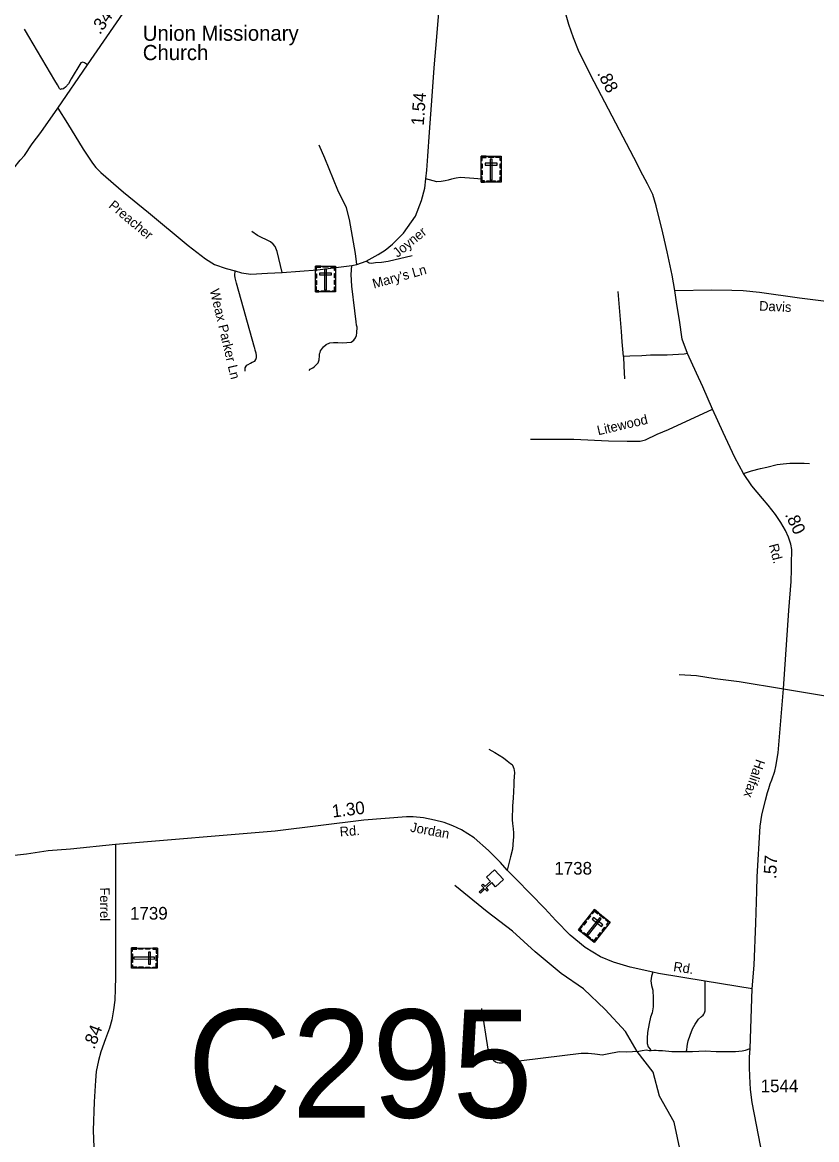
# Model space of a CAD drawing. Extents: x 2220236 to 2384410, y 720751 to 894131.
# Drawn here: x 2332948 to 2340787, y 767564 to 778583 of the extents above; entities that cross this region are included whole.
import ezdxf

# ---------------------------------------------------------------- set-up
doc = ezdxf.new("R2010")
doc.units = 0
doc.layers.add('Default', color=7, linetype='Continuous')

msp = doc.modelspace()

# ---------------------------------------------------------------- linework, layer by layer
at = {"layer": 'Default'}
for points in [[(2333299, 777738), (2333591, 778165), (2333943, 778675), (2334238, 779104), (2334327, 779223)], [(2333299, 777738), (2333395, 777586), (2333549, 777333), (2333641, 777194), (2333675, 777150), (2333722, 777102), (2333946, 776908), (2334192, 776707), (2334584, 776381), (2334757, 776249), (2334846, 776196), (2334961, 776155), (2335050, 776131), (2335111, 776112), (2335204, 776101), (2335367, 776108), (2335511, 776117), (2335861, 776142), (2336199, 776186), (2336248, 776194), (2336342, 776229), (2336459, 776293), (2336528, 776336), (2336600, 776395), (2336710, 776503), (2336827, 776670), (2336886, 776825), (2336919, 776948), (2336931, 777039), (2336941, 777124), (2336950, 777262), (2336967, 777500), (2336994, 777854), (2337013, 778133), (2337040, 778439), (2337070, 778840)], [(2339388, 775939), (2339362, 776088), (2339312, 776320), (2339270, 776507), (2339202, 776774), (2339169, 776885), (2339116, 776991), (2339072, 777077), (2338984, 777249), (2338590, 777996), (2338515, 778143), (2338438, 778306), (2338387, 778429), (2338341, 778560), (2338291, 778736)], [(2333591, 778165), (2333561, 778183), (2333544, 778189), (2333537, 778188), (2333527, 778182), (2333431, 778025), (2333404, 777978), (2333374, 777943), (2333357, 777931), (2333349, 777925), (2333339, 777926), (2333326, 777921), (2333315, 777931), (2333294, 777966), (2333270, 778009), (2332969, 778514)], [(2331904, 776214), (2331951, 776264), (2332056, 776374), (2332110, 776417), (2332152, 776461), (2332191, 776495), (2332228, 776529), (2332263, 776561), (2332325, 776621), (2332388, 776676), (2332460, 776743), (2332592, 776865), (2332660, 776932), (2332690, 776962), (2332713, 776987), (2332745, 777021), (2332811, 777088), (2332864, 777146), (2332928, 777223), (2332971, 777271), (2333046, 777384), (2333130, 777498), (2333299, 777738)], [(2336248, 776194), (2336235, 776302), (2336177, 776639), (2336146, 776752), (2336063, 776929), (2335934, 777244), (2335878, 777373)], [(2337482, 777037), (2337405, 777044), (2337273, 777052), (2337230, 777046), (2337182, 777035), (2337152, 777025), (2337120, 777020), (2337080, 777012), (2337040, 777011), (2336931, 777039)], [(2335511, 776117), (2335464, 776323), (2335442, 776371), (2335425, 776395), (2335397, 776417), (2335269, 776481), (2335213, 776519)], [(2336795, 776280), (2336560, 776224), (2336491, 776215), (2336432, 776210), (2336395, 776203), (2336370, 776207), (2336342, 776229)], [(2335778, 775151), (2335790, 775161), (2335814, 775175), (2335833, 775189), (2335867, 775226), (2335879, 775256), (2335882, 775294), (2335882, 775314), (2335886, 775328), (2335892, 775344), (2335902, 775357), (2335920, 775382), (2335921, 775382), (2335948, 775407), (2335983, 775421), (2336019, 775426), (2336061, 775426), (2336108, 775423), (2336192, 775430), (2336221, 775450), (2336237, 775470), (2336245, 775494), (2336248, 775520), (2336252, 775578), (2336245, 775598), (2336242, 775629), (2336231, 775737), (2336199, 775981), (2336192, 776095), (2336199, 776186)], [(2335146, 775143), (2335148, 775175), (2335156, 775193), (2335164, 775201), (2335178, 775209), (2335199, 775222), (2335215, 775230), (2335242, 775242), (2335253, 775259), (2335258, 775278), (2335258, 775297), (2335255, 775320), (2335246, 775351), (2335242, 775370), (2335241, 775377), (2335061, 776010), (2335048, 776063), (2335046, 776086), (2335050, 776131)], [(2339388, 775939), (2339752, 775944), (2339950, 775943), (2340062, 775938), (2340222, 775922), (2340619, 775867), (2341406, 775766)], [(2340458, 772010), (2340511, 772783), (2340534, 773068), (2340540, 773186), (2340540, 773240), (2340543, 773385), (2340533, 773437), (2340508, 773506), (2340478, 773570), (2340434, 773649), (2340380, 773728), (2340307, 773821), (2340251, 773887), (2340148, 774013), (2340066, 774135), (2339978, 774291), (2339864, 774538), (2339759, 774769), (2339664, 774987), (2339601, 775123), (2339511, 775317), (2339460, 775458), (2339432, 775647), (2339408, 775799), (2339388, 775939)], [(2338882, 775287), (2338866, 775433), (2338861, 775533), (2338827, 775929)], [(2339511, 775317), (2339479, 775311), (2339425, 775306), (2339310, 775301), (2339146, 775299), (2339060, 775295), (2338944, 775291), (2338882, 775287)], [(2338882, 775287), (2338883, 775193), (2338891, 775066)], [(2337963, 774472), (2338392, 774471), (2338732, 774455), (2338917, 774451), (2338998, 774453), (2339046, 774453), (2339099, 774467), (2339214, 774523), (2339324, 774568), (2339759, 774769)], [(2340066, 774135), (2340145, 774161), (2340232, 774182), (2340294, 774195), (2340397, 774221), (2340457, 774229), (2340523, 774234), (2340589, 774237), (2340663, 774236), (2340717, 774232)], [(2339431, 772150), (2339602, 772142), (2339785, 772113), (2340023, 772081), (2340458, 772010)], [(2340150, 769052), (2340171, 769284), (2340187, 769700), (2340196, 770016), (2340200, 770157), (2340228, 770655), (2340245, 770764), (2340281, 770911), (2340302, 770988), (2340315, 771026), (2340328, 771072), (2340343, 771114), (2340373, 771199), (2340383, 771244), (2340407, 771378), (2340415, 771459), (2340458, 772010)], [(2340458, 772010), (2343353, 771527), (2343573, 771495), (2343812, 771451)], [(2337551, 771416), (2337612, 771382), (2337697, 771328), (2337733, 771300), (2337767, 771275), (2337781, 771263), (2337792, 771242), (2337800, 771224), (2337805, 771184), (2337800, 771100), (2337799, 771062), (2337794, 770996), (2337791, 770931), (2337786, 770855), (2337781, 770718), (2337784, 770681), (2337787, 770656), (2337791, 770631), (2337794, 770589), (2337795, 770547), (2337791, 770519), (2337784, 770429), (2337765, 770352), (2337734, 770222)], [(2333869, 770476), (2333425, 770429), (2333204, 770411), (2332990, 770380), (2332365, 770309), (2332145, 770287), (2332083, 770284), (2331985, 770285), (2331867, 770304), (2331759, 770325), (2331647, 770356), (2331534, 770399), (2331422, 770447), (2331331, 770496), (2331223, 770569), (2331114, 770648), (2331027, 770713), (2330897, 770816)], [(2340150, 769052), (2339688, 769128), (2339226, 769204), (2339169, 769217), (2338946, 769265), (2338782, 769316), (2338654, 769368), (2338504, 769459), (2338356, 769580), (2338214, 769724), (2338103, 769845), (2337821, 770134), (2337734, 770222), (2337667, 770296), (2337550, 770415), (2337407, 770541), (2337281, 770619), (2337195, 770658), (2337111, 770692), (2337016, 770716), (2336907, 770737), (2336804, 770748), (2336740, 770748), (2336319, 770715), (2335443, 770608), (2333869, 770476)], [(2333869, 770476), (2333869, 769168), (2333866, 769052), (2333861, 768940), (2333848, 768844), (2333830, 768746), (2333807, 768664), (2333768, 768560), (2333724, 768430), (2333700, 768346), (2333676, 768235), (2333669, 768146), (2333656, 767936), (2333647, 767656), (2333688, 766661), (2333684, 766078)], [(2339448, 767426), (2339379, 767737), (2339237, 767994), (2339172, 768229), (2339014, 768435), (2338900, 768631), (2338699, 768848), (2338485, 769051), (2338266, 769204), (2338009, 769418), (2337784, 769621), (2337536, 769810), (2337217, 770071)], [(2339169, 769217), (2339157, 769175), (2339152, 769129), (2339157, 769084), (2339170, 769037), (2339173, 768961), (2339175, 768874), (2339164, 768816), (2339147, 768771), (2339135, 768710), (2339119, 768621), (2339114, 768565), (2339114, 768514), (2339124, 768481), (2339140, 768460), (2339151, 768445)], [(2339498, 768433), (2339505, 768451), (2339510, 768484), (2339512, 768507), (2339519, 768538), (2339538, 768594), (2339563, 768657), (2339587, 768704), (2339622, 768753), (2339650, 768778), (2339667, 768792), (2339674, 768801), (2339681, 768815), (2339687, 768834), (2339687, 768869), (2339687, 769028), (2339688, 769128)], [(2340254, 767387), (2340151, 767932), (2340134, 768060), (2340129, 768125), (2340126, 768191), (2340124, 768275), (2340124, 768376), (2340130, 768462), (2340150, 769052)], [(2337479, 768856), (2337542, 768457), (2337554, 768421), (2337570, 768393), (2337597, 768349), (2337617, 768331), (2337635, 768324), (2337654, 768322), (2337685, 768321), (2338462, 768416), (2338533, 768417), (2338599, 768411), (2338623, 768406), (2338647, 768404), (2338670, 768401), (2338721, 768409), (2338837, 768432), (2338908, 768430), (2339031, 768437), (2339065, 768444), (2339108, 768449), (2339134, 768445), (2339151, 768445)], [(2339151, 768445), (2339155, 768445), (2339179, 768446), (2339202, 768447), (2339227, 768445), (2339265, 768445), (2339356, 768435), (2339423, 768433), (2339498, 768433)], [(2339498, 768433), (2339563, 768433), (2339685, 768441), (2339796, 768433), (2339901, 768433), (2339986, 768435), (2340053, 768440), (2340085, 768448), (2340130, 768462)]]:
    msp.add_lwpolyline(points, dxfattribs=at)
for points in [[(2337475, 777262), (2337674, 777262), (2337674, 777008), (2337475, 777008)], [(2337475, 777219), (2337486, 777219), (2337486, 777251), (2337527, 777251), (2337527, 777262), (2337475, 777262)], [(2337549, 777262), (2337601, 777262), (2337601, 777251), (2337549, 777251)], [(2337674, 777219), (2337663, 777219), (2337663, 777251), (2337622, 777251), (2337622, 777262), (2337674, 777262)], [(2337475, 777145), (2337475, 777188), (2337486, 777188), (2337486, 777145)], [(2337516, 777194), (2337516, 777176), (2337634, 777176), (2337634, 777194)], [(2337584, 777233), (2337565, 777233), (2337565, 777030), (2337584, 777030)], [(2337663, 777146), (2337663, 777189), (2337674, 777189), (2337674, 777146)], [(2337475, 777078), (2337475, 777121), (2337486, 777121), (2337486, 777078)], [(2337508, 777008), (2337508, 777019), (2337486, 777019), (2337486, 777060), (2337475, 777060), (2337475, 777008)], [(2337641, 777008), (2337641, 777019), (2337663, 777019), (2337663, 777060), (2337674, 777060), (2337674, 777008)], [(2337663, 777080), (2337663, 777123), (2337674, 777123), (2337674, 777080)], [(2337532, 777019), (2337617, 777019), (2337617, 777008), (2337532, 777008)], [(2335841, 776179), (2336040, 776179), (2336040, 775924), (2335841, 775924)], [(2335841, 776135), (2335852, 776135), (2335852, 776167), (2335893, 776167), (2335893, 776179), (2335841, 776179)], [(2335915, 776178), (2335967, 776178), (2335967, 776167), (2335915, 776167)], [(2336040, 776135), (2336028, 776135), (2336028, 776167), (2335988, 776167), (2335988, 776178), (2336040, 776178)], [(2335841, 776061), (2335841, 776104), (2335852, 776104), (2335852, 776061)], [(2335881, 776110), (2335881, 776092), (2335999, 776092), (2335999, 776110)], [(2335950, 776149), (2335931, 776149), (2335931, 775946), (2335950, 775946)], [(2336028, 776062), (2336028, 776105), (2336040, 776105), (2336040, 776062)], [(2335841, 775994), (2335841, 776037), (2335852, 776037), (2335852, 775994)], [(2335874, 775924), (2335874, 775935), (2335852, 775935), (2335852, 775976), (2335841, 775976), (2335841, 775924)], [(2336007, 775924), (2336007, 775935), (2336029, 775935), (2336029, 775976), (2336040, 775976), (2336040, 775924)], [(2336028, 775996), (2336028, 776039), (2336040, 776039), (2336040, 775996)], [(2335898, 775935), (2335983, 775935), (2335983, 775924), (2335898, 775924)], [(2337619, 770058), (2337580, 770100), (2337524, 770048), (2337546, 770024), (2337534, 770014), (2337512, 770037), (2337468, 769996), (2337457, 770008), (2337501, 770049), (2337480, 770072), (2337491, 770083), (2337513, 770060), (2337569, 770111), (2337530, 770154), (2337608, 770226), (2337697, 770130)], [(2338594, 769833), (2338750, 769710), (2338592, 769510), (2338436, 769634)], [(2338521, 769741), (2338548, 769775), (2338557, 769768), (2338530, 769734)], [(2338567, 769799), (2338576, 769792), (2338596, 769818), (2338627, 769792), (2338634, 769801), (2338594, 769833)], [(2338652, 769787), (2338692, 769755), (2338685, 769746), (2338645, 769778)], [(2338462, 769613), (2338469, 769622), (2338451, 769636), (2338477, 769668), (2338468, 769674), (2338436, 769634)], [(2338479, 769689), (2338506, 769723), (2338515, 769715), (2338488, 769681)], [(2338661, 769743), (2338646, 769754), (2338520, 769595), (2338535, 769584)], [(2338583, 769755), (2338572, 769740), (2338664, 769667), (2338676, 769682)], [(2338669, 769626), (2338695, 769660), (2338704, 769652), (2338678, 769618)], [(2338723, 769676), (2338714, 769683), (2338734, 769708), (2338702, 769733), (2338709, 769742), (2338750, 769710)], [(2338488, 769607), (2338554, 769554), (2338547, 769545), (2338481, 769598)], [(2338566, 769531), (2338573, 769540), (2338590, 769526), (2338615, 769558), (2338624, 769551), (2338592, 769510)], [(2338628, 769574), (2338655, 769608), (2338663, 769601), (2338637, 769567)], [(2334281, 769454), (2334280, 769255), (2334025, 769256), (2334026, 769455)], [(2334026, 769422), (2334037, 769422), (2334037, 769444), (2334078, 769443), (2334078, 769455), (2334026, 769455)], [(2334096, 769454), (2334139, 769454), (2334139, 769443), (2334096, 769443)], [(2334163, 769454), (2334206, 769454), (2334206, 769443), (2334163, 769443)], [(2334237, 769454), (2334237, 769442), (2334269, 769442), (2334269, 769402), (2334280, 769402), (2334281, 769454)], [(2334037, 769397), (2334037, 769312), (2334025, 769312), (2334026, 769397)], [(2334251, 769345), (2334251, 769363), (2334048, 769364), (2334048, 769346)], [(2334212, 769413), (2334194, 769413), (2334193, 769295), (2334212, 769295)], [(2334280, 769380), (2334280, 769328), (2334269, 769328), (2334269, 769380)], [(2334025, 769289), (2334037, 769289), (2334037, 769267), (2334077, 769267), (2334077, 769255), (2334025, 769256)], [(2334097, 769267), (2334141, 769267), (2334141, 769255), (2334097, 769255)], [(2334163, 769266), (2334207, 769266), (2334207, 769255), (2334163, 769255)], [(2334236, 769255), (2334236, 769266), (2334269, 769266), (2334269, 769306), (2334280, 769306), (2334280, 769254)]]:
    msp.add_lwpolyline(points, close=True, dxfattribs=at)

# ---------------------------------------------------------------- texts
for s, height, rotation, p in [('.34', 125, 55.3413, (2333715, 778455)), ('.88', 125, 297.8159, (2338617, 778080)), ('1.54', 125, 85.74, (2336909, 777562)), ('Preacher', 95, 320.0942, (2333793, 776764)), ('Joyner', 95, 39.2052, (2336651, 776259)), ("Mary's Ln", 95, 15.5998, (2336418, 775957)), ('Weax Parker Ln', 95, 283.3869, (2334797, 775942)), ('Davis', 95, 357.6503, (2340218, 775740)), ('Litewood', 95, 13.092, (2338632, 774510)), ('.80', 125, 295.3934, (2340471, 773729)), ('Rd.', 95, 284.7528, (2340314, 773428)), ('Halifax', 95, 250.9785, (2340191, 771323)), ('1.30', 125, 6.9575, (2336011, 770740)), ('Rd.', 95, 4.4775, (2336084, 770553)), ('Jordan', 95, 349.3708, (2336771, 770603)), ('.57', 125, 86.6736, (2340386, 770133)), ('Ferrel', 95, 270.4224, (2333714, 770051)), ('Rd.', 95, 351.6018, (2339368, 769226)), ('.84', 125, 69.3336, (2333659, 768449))]:
    msp.add_text(s, height=height, rotation=rotation, dxfattribs=at).set_placement(p)
for s, height, p in [('Union Missionary', 150, (2334137, 778401)), ('Church', 150, (2334137, 778210)), ('1738', 125, (2338198, 770178)), ('1739', 125, (2334011, 769734)), ('C295', 1066.3, (2334576, 767781)), ('1544', 125, (2340234, 768032))]:
    msp.add_text(s, height=height, dxfattribs=at).set_placement(p)

doc.saveas('drawing.dxf')
